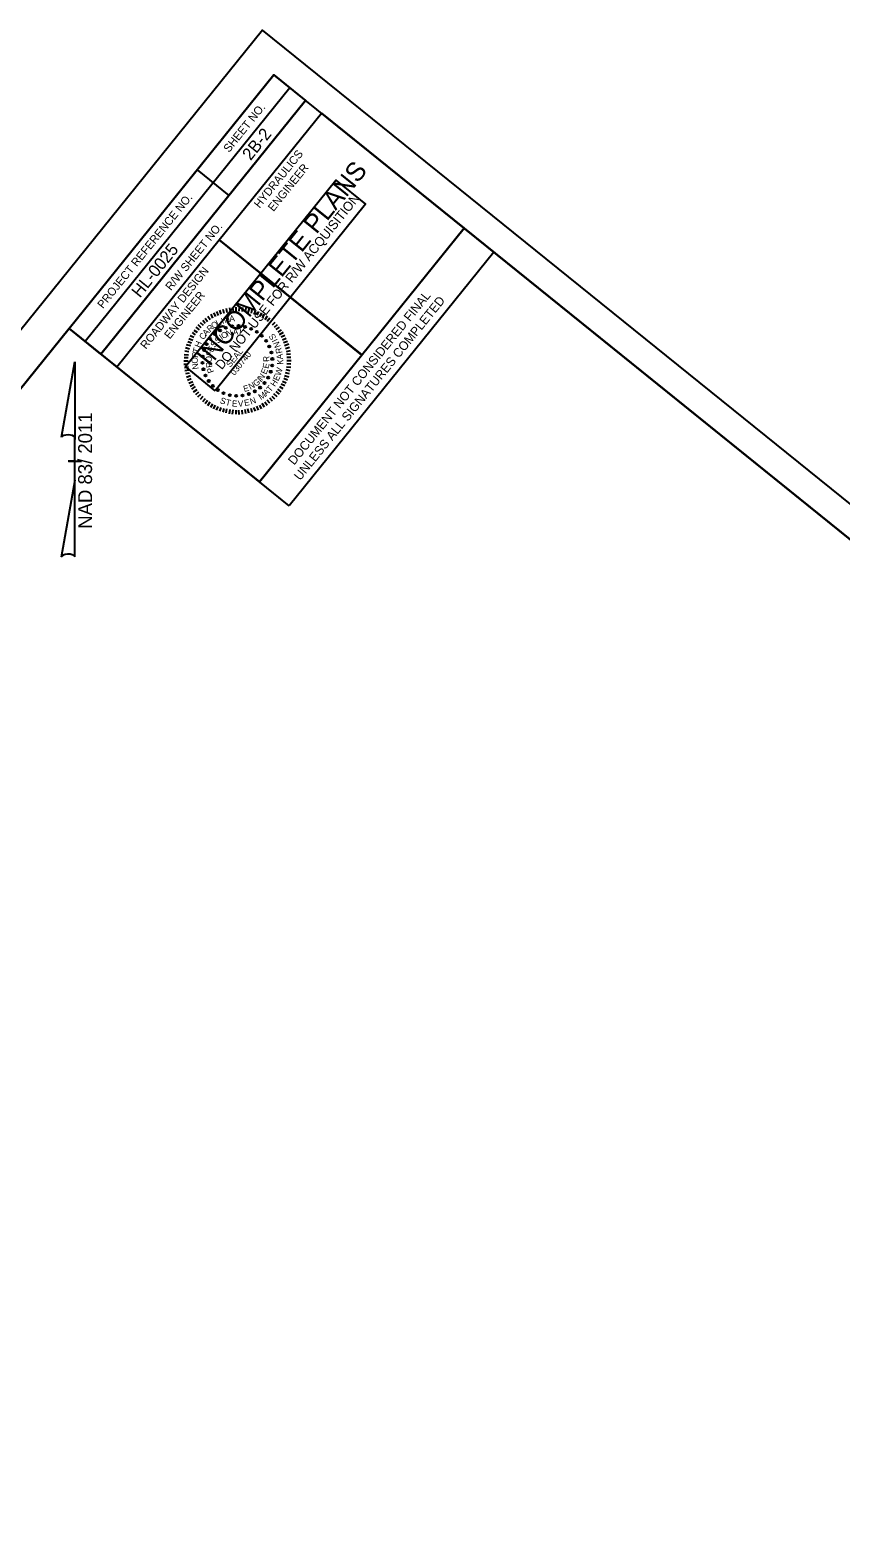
# Model space of a CAD drawing. Extents: x 1487845 to 1489754, y 498370 to 500368.
# Drawn here: x 1488759 to 1489256, y 499442 to 500368 of the extents above; entities that cross this region are included whole.
import ezdxf

# ---------------------------------------------------------------- set-up
doc = ezdxf.new("R2010")
doc.units = 0
for name, color, linetype in [('Old_Level_9', 7, 'Continuous'), ('Prop North Arrow NAD83 for Plan Sheets CELL', 7, 'Continuous'), ('Sheet Border Standard 30in CELL', 7, 'Continuous'), ('Sheet Clip Boundary CELL', 7, 'Continuous'), ('Sheet Data Field CELL', 7, 'Continuous'), ('Sheet Plan CELL', 7, 'Continuous'), ('Sheet Plot Border Outside CELL', 7, 'Continuous'), ('Sheet Sticker Exception Certification CELL', 7, 'Continuous'), ('Sheet Sticker Incomplete CELL', 7, 'Continuous')]:
    doc.layers.add(name, color=color, linetype=linetype)

msp = doc.modelspace()

# ---------------------------------------------------------------- linework, layer by layer
at = {"layer": 'Old_Level_9'}
for p, q in [((1488881.05, 500197.35), (1488881.45, 500194.97)), ((1488882.95, 500197.62), (1488883.29, 500195.03)), ((1488885.07, 500197.71), (1488885.12, 500195.23)), ((1488887.13, 500197.72), (1488886.9, 500195.2)), ((1488889.07, 500197.57), (1488888.84, 500195.06)), ((1488891.08, 500197.36), (1488890.71, 500194.83)), ((1488893.11, 500197.01), (1488892.46, 500194.45)), ((1488863.17, 500188.39), (1488864.91, 500186.73)), ((1488864.72, 500189.84), (1488866.28, 500187.94)), ((1488866.22, 500191.07), (1488867.65, 500189.02)), ((1488867.88, 500192.17), (1488869.31, 500190.12)), ((1488869.67, 500193.43), (1488870.78, 500190.99)), ((1488871.36, 500194.25), (1488872.59, 500192.1)), ((1488873.11, 500195.15), (1488874.23, 500192.71)), ((1488875.08, 500196), (1488875.85, 500193.45)), ((1488877.1, 500196.43), (1488877.72, 500194.01)), ((1488879.04, 500196.92), (1488879.59, 500194.42)), ((1488894.94, 500196.56), (1488894.49, 500194.1)), ((1488897.07, 500195.87), (1488896.06, 500193.34)), ((1488898.93, 500195.14), (1488897.9, 500192.76)), ((1488900.72, 500194.34), (1488899.54, 500192.08)), ((1488902.39, 500193.38), (1488901.27, 500191.2)), ((1488904.15, 500192.22), (1488902.75, 500190)), ((1488905.85, 500190.97), (1488904.28, 500189.03)), ((1488907.33, 500189.78), (1488905.76, 500187.84)), ((1488908.9, 500188.39), (1488907.23, 500186.64)), ((1488856.18, 500178.61), (1488858.57, 500177.59)), ((1488857.06, 500180.34), (1488859.24, 500179.23)), ((1488858.15, 500182.17), (1488860.14, 500180.82)), ((1488859.26, 500183.71), (1488861.32, 500182.43)), ((1488860.42, 500185.47), (1488862.45, 500183.84)), ((1488861.74, 500187.1), (1488863.58, 500185.24)), ((1488910.41, 500186.91), (1488908.51, 500185.36)), ((1488911.7, 500185.49), (1488909.58, 500183.98)), ((1488912.86, 500183.9), (1488910.75, 500182.4)), ((1488914.04, 500182.18), (1488911.71, 500180.72)), ((1488915.1, 500180.3), (1488912.78, 500179.34)), ((1488915.92, 500178.61), (1488913.68, 500177.59)), ((1488853.65, 500171.02), (1488856.27, 500170.44)), ((1488854.16, 500172.92), (1488856.51, 500172.18)), ((1488854.6, 500174.75), (1488857.23, 500174.17)), ((1488855.46, 500176.76), (1488857.76, 500175.8)), ((1488916.77, 500176.64), (1488914.3, 500175.81)), ((1488917.45, 500174.94), (1488914.92, 500174.03)), ((1488917.88, 500172.92), (1488915.47, 500172.16)), ((1488918.31, 500170.9), (1488915.87, 500170.43)), ((1488853.18, 500164.85), (1488855.81, 500164.78)), ((1488853.18, 500162.79), (1488855.67, 500162.84)), ((1488853.25, 500166.85), (1488855.74, 500166.76)), ((1488853.39, 500168.78), (1488856.05, 500168.57)), ((1488853.47, 500160.76), (1488855.92, 500161.09)), ((1488918.67, 500168.81), (1488916.07, 500168.6)), ((1488918.75, 500160.78), (1488916.1, 500161)), ((1488918.96, 500164.86), (1488916.25, 500164.85)), ((1488918.75, 500162.84), (1488916.25, 500162.93)), ((1488918.81, 500166.9), (1488916.4, 500166.79)), ((1488853.68, 500158.79), (1488856.2, 500159.2)), ((1488854.24, 500156.93), (1488856.68, 500157.4)), ((1488854.74, 500154.85), (1488857.14, 500155.75)), ((1488855.3, 500152.99), (1488857.69, 500153.88)), ((1488856.15, 500151.02), (1488858.59, 500152.13)), ((1488915.87, 500151.16), (1488913.63, 500152.2)), ((1488916.75, 500152.89), (1488914.51, 500153.93)), ((1488917.46, 500154.88), (1488914.89, 500155.68)), ((1488918.03, 500156.87), (1488915.48, 500157.52)), ((1488918.4, 500158.75), (1488915.92, 500159.34)), ((1488857.05, 500149.26), (1488859.33, 500150.5)), ((1488858.03, 500147.45), (1488860.28, 500148.97)), ((1488859.13, 500145.79), (1488861.24, 500147.3)), ((1488860.45, 500144.08), (1488862.41, 500145.71)), ((1488861.74, 500142.66), (1488863.54, 500144.41)), ((1488863.25, 500141.18), (1488864.96, 500143.14)), ((1488864.67, 500139.91), (1488866.39, 500141.73)), ((1488907.47, 500139.95), (1488905.84, 500141.9)), ((1488908.9, 500141.24), (1488907.22, 500142.98)), ((1488910.37, 500142.75), (1488908.41, 500144.46)), ((1488911.77, 500144.32), (1488909.82, 500145.89)), ((1488912.88, 500145.86), (1488910.74, 500147.34)), ((1488913.98, 500147.54), (1488911.93, 500148.81)), ((1488915.07, 500149.36), (1488912.81, 500150.55)), ((1488866.3, 500138.59), (1488867.71, 500140.66)), ((1488867.92, 500137.41), (1488869.32, 500139.63)), ((1488869.6, 500136.32), (1488870.86, 500138.51)), ((1488871.35, 500135.29), (1488872.45, 500137.62)), ((1488873.2, 500134.57), (1488874.24, 500136.81)), ((1488875.12, 500133.92), (1488876.08, 500136.23)), ((1488877.18, 500133.29), (1488877.78, 500135.63)), ((1488879.01, 500132.84), (1488879.53, 500135.25)), ((1488881.05, 500132.35), (1488881.56, 500134.89)), ((1488882.92, 500132.12), (1488883.29, 500134.65)), ((1488885.14, 500132.01), (1488885.15, 500134.57)), ((1488887.14, 500131.94), (1488886.93, 500134.54)), ((1488889.05, 500132.07), (1488888.91, 500134.62)), ((1488891.14, 500132.44), (1488890.66, 500134.87)), ((1488893.03, 500132.71), (1488892.4, 500135.27)), ((1488895.05, 500133.14), (1488894.35, 500135.62)), ((1488897.03, 500133.85), (1488896.14, 500136.24)), ((1488898.88, 500134.54), (1488897.84, 500136.92)), ((1488900.71, 500135.38), (1488899.69, 500137.62)), ((1488902.52, 500136.36), (1488901.28, 500138.64)), ((1488904.26, 500137.4), (1488902.9, 500139.53)), ((1488905.89, 500138.78), (1488904.34, 500140.68))]:
    msp.add_line(p, q, dxfattribs=at)
for centre in [(1488869.3, 500178.3), (1488872.08, 500181.14), (1488875.33, 500183.41), (1488878.94, 500185.05), (1488882.79, 500186), (1488886.75, 500186.22), (1488890.68, 500185.71), (1488894.45, 500184.49), (1488897.94, 500182.6), (1488901.02, 500180.1), (1488865.53, 500171.36), (1488867.1, 500175.01), (1488903.58, 500177.07), (1488905.55, 500173.63), (1488906.84, 500169.88), (1488864.53, 500163.53), (1488864.67, 500167.49), (1488865.11, 500159.61), (1488907.29, 500162), (1488907.43, 500165.96), (1488866.41, 500155.86), (1488868.38, 500152.42), (1488902.65, 500151.19), (1488904.86, 500154.49), (1488906.42, 500158.13), (1488870.94, 500149.39), (1488874.02, 500146.89), (1488877.51, 500145), (1488881.28, 500143.78), (1488885.21, 500143.27), (1488889.17, 500143.5), (1488893.02, 500144.44), (1488896.63, 500146.08), (1488899.88, 500148.36)]:
    msp.add_circle(centre, 0.63, dxfattribs=at)
at = {"layer": 'Prop North Arrow NAD83 for Plan Sheets CELL'}
for p, q in [((1488777.99, 500117.89), (1488786.19, 500164.24)), ((1488786.24, 500164.24), (1488786.19, 500164.24)), ((1488786.24, 500164.24), (1488786.19, 500164.24)), ((1488786.24, 500164.24), (1488786.24, 500116.44)), ((1488786.24, 500091.64), (1488786.24, 500117.84)), ((1488786.24, 500116.44), (1488786.24, 500117.79)), ((1488782.24, 500103.24), (1488782.19, 500103.24)), ((1488785.79, 500103.24), (1488782.24, 500103.24)), ((1488782.29, 500103.24), (1488790.29, 500103.24)), ((1488786.24, 500091.64), (1488777.89, 500044.39)), ((1488786.29, 500044.59), (1488786.24, 500091.64))]:
    msp.add_line(p, q, dxfattribs=at)
for centre, start_param, end_param in [((1488782.12, 500117.39), 0.216388, 2.908219), ((1488782.12, 500044.22), 0.201328, 3.141593)]:
    msp.add_ellipse(centre, major_axis=(4.23, -0.03), ratio=0.461098, start_param=start_param, end_param=end_param, dxfattribs=at)
at = {"layer": 'Sheet Border Standard 30in CELL'}
msp.add_line((1488802.23, 500168.98), (1488811.96, 500161.13), dxfattribs=at)
at = {"layer": 'Sheet Clip Boundary CELL'}
msp.add_lwpolyline([(1488917.84, 500075.78), (1488782.72, 500184.72), (1488048.03, 499273.68), (1488893.23, 498649.1), (1489725.65, 499681.3), (1489043.41, 500231.49)], close=True, dxfattribs=at)
at = {"layer": 'Sheet Plan CELL'}
for p, q in [((1488792.49, 500176.83), (1488918.08, 500332.55)), ((1488802.25, 500168.97), (1488927.81, 500324.7)), ((1488802.25, 500168.97), (1488927.81, 500324.7)), ((1488861.26, 500281.99), (1488880.75, 500266.33)), ((1488874.78, 500239.01), (1488962.33, 500168.43)), ((1488802.25, 500168.97), (1488811.97, 500161.13))]:
    msp.add_line(p, q, dxfattribs=at)
for points in [[(1488908.33, 500340.46), (1487966.68, 499172.8), (1488784.02, 498513.67), (1489725.65, 499681.3)], [(1488782.72, 500184.72), (1488908.33, 500340.46), (1488927.81, 500324.7), (1488802.25, 500168.97)], [(1488874.78, 500239.01), (1488937.54, 500316.85), (1489025.13, 500246.23), (1488962.36, 500168.38)], [(1488784.02, 498513.67), (1487966.69, 499172.77), (1488782.72, 500184.72), (1488899.54, 500090.53), (1489025.13, 500246.23), (1489725.65, 499681.3)], [(1488811.97, 500161.13), (1488874.78, 500239.01), (1488962.36, 500168.38), (1488899.54, 500090.53)]]:
    msp.add_lwpolyline(points, close=True, dxfattribs=at)
at = {"layer": 'Sheet Plot Border Outside CELL'}
msp.add_lwpolyline([(1488697.03, 498369.94), (1489753.85, 499680.4), (1488901.48, 500367.79), (1487844.66, 499057.32)], close=True, dxfattribs=at)
at = {"layer": 'Sheet Sticker Exception Certification CELL'}
for p, q in [((1488899.54, 500090.53), (1489025.12, 500246.24)), ((1488899.54, 500090.53), (1489025.12, 500246.24)), ((1489025.13, 500246.23), (1489043.42, 500231.48)), ((1489025.13, 500246.23), (1489043.42, 500231.48)), ((1489043.41, 500231.49), (1488917.84, 500075.78)), ((1489043.41, 500231.49), (1488917.84, 500075.78)), ((1488917.84, 500075.78), (1488899.54, 500090.53)), ((1488917.84, 500075.78), (1488899.54, 500090.53))]:
    msp.add_line(p, q, dxfattribs=at)
at = {"layer": 'Sheet Sticker Incomplete CELL'}
msp.add_lwpolyline([(1488872.43, 500146.49), (1488854.13, 500161.24), (1488946.41, 500275.67), (1488964.7, 500260.92)], close=True, dxfattribs=at)

# ---------------------------------------------------------------- texts
at = {"layer": 'Old_Level_9'}
for s, height, rotation, p in [('O', 3.78, 34.20245, (1488871.37, 500184.22)), ('L', 3.78, 26.86155, (1488873.95, 500185.99)), ('I', 3.78, 21.9216, (1488876.86, 500187.37)), ('N', 3.78, 16.01949, (1488878.22, 500187.94)), ('A', 3.78, 8.12072, (1488881.27, 500188.7)), ('C', 3.78, 56.05556, (1488865.27, 500177.45)), ('A', 3.78, 49.09051, (1488866.93, 500179.84)), ('R', 3.78, 41.1372, (1488869.16, 500182.28)), ('S', 3.76, 44.1571, (1488874.11, 500175.2)), ('I', 3.76, 36.59771, (1488876.43, 500177.44)), ('O', 3.76, 28.99053, (1488877.22, 500178.09)), ('N', 3.76, 18.50867, (1488879.77, 500179.5)), ('A', 3.76, 5.05942, (1488883.28, 500180.52)), ('L', 3.76, 352.64795, (1488886.89, 500180.69)), ('S', 3.78, 123.37353, (1488910.01, 500179.11)), ('R', 3.78, 83.2911, (1488861.74, 500166.55)), ('T', 3.78, 76.55143, (1488862.16, 500169.3)), ('H', 3.78, 68.859, (1488863.01, 500172.59)), ('F', 3.76, 77.5156, (1488870.4, 500167.41)), ('E', 3.76, 67.70458, (1488870.92, 500169.81)), ('S', 3.76, 55.58367, (1488872.18, 500172.65)), ('SEAL', 3.759, 51.11565, (1488881.61, 500160.5)), ('030740', 3.759, 51.11565, (1488884.24, 500155.54)), ('I', 3.78, 117.16204, (1488910.89, 500177.51)), ('N', 3.78, 110.48821, (1488912.63, 500173.62)), ('R', 3.78, 102.26596, (1488913.61, 500169.67)), ('A', 3.78, 94.63734, (1488913.96, 500165.84)), ('O', 3.78, 91.05986, (1488861.68, 500163.13)), ('N', 3.78, 99.1823, (1488862.25, 500159.85)), ('O', 3.76, 89.36746, (1488870.21, 500163.83)), ('R', 3.76, 100.86345, (1488870.73, 500160.97)), ('P', 3.76, 111.23929, (1488871.75, 500158.09)), ('E', 3.76, 66.92133, (1488903.6, 500156.17)), ('E', 3.76, 78.27246, (1488905.07, 500159.74)), ('R', 3.76, 91.46491, (1488905.59, 500164.21)), ('W', 3.78, 73.12141, (1488912.48, 500155.37)), ('K', 3.78, 87.25665, (1488914.07, 500162.37)), ('N', 3.76, 27.17401, (1488893.91, 500147.03)), ('G', 3.76, 38.59689, (1488897.36, 500148.75)), ('I', 3.76, 46.74023, (1488900.41, 500151.42)), ('N', 3.76, 54.24344, (1488901.17, 500152.36)), ('H', 3.78, 57.12686, (1488909.04, 500148.64)), ('E', 3.78, 65.2804, (1488911.06, 500152.07)), ('S', 3.78, 339.32765, (1488874.95, 500139)), ('E', 3.76, 15.98484, (1488890.22, 500145.64)), ('N', 3.78, 19.44464, (1488894.36, 500137.92)), ('M', 3.78, 33.45268, (1488900.4, 500140.64)), ('A', 3.78, 41.29781, (1488903.65, 500143.02)), ('T', 3.78, 48.50223, (1488906.22, 500145.32)), ('T', 3.78, 346.74003, (1488878.44, 500137.72)), ('E', 3.78, 354.93814, (1488882.48, 500136.86)), ('V', 3.78, 3.04544, (1488886.37, 500136.63)), ('E', 3.78, 11.34689, (1488890.5, 500137.01))]:
    msp.add_text(s, height=height, rotation=rotation, dxfattribs=at).set_placement(p)
at = {"layer": 'Prop North Arrow NAD83 for Plan Sheets CELL'}
msp.add_text('NAD 83/ 2011', height=8.5, rotation=90, dxfattribs=at).set_placement((1488796.76, 500061.72))
at = {"layer": 'Sheet Data Field CELL'}
for s, p in [('2B-2', (1488894.07, 500287.32)), ('HL-0025', (1488826.16, 500203.02))]:
    msp.add_text(s, height=7.5, rotation=51.11565, dxfattribs=at).set_placement(p)
at = {"layer": 'Sheet Plan CELL'}
for s, height, p in [('SHEET NO.', 5, (1488880.85, 500292.33)), ('HYDRAULICS', 5, (1488899.57, 500258.16)), ('ENGINEER', 5, (1488908.13, 500256.09)), ('PROJECT REFERENCE NO.', 5.0001, (1488803.45, 500196.53)), ('R/W SHEET NO.', 5.0001, (1488845.19, 500207.58)), ('ROADWAY DESIGN', 5.0001, (1488829.82, 500171.63)), ('ENGINEER', 5, (1488844.47, 500177.79))]:
    msp.add_text(s, height=height, rotation=51.11565, dxfattribs=at).set_placement(p)
at = {"layer": 'Sheet Sticker Exception Certification CELL'}
for s, p in [('DOCUMENT NOT CONSIDERED FINAL', (1488920.82, 500100.44)), ('DOCUMENT NOT CONSIDERED FINAL', (1488920.82, 500100.44)), ('UNLESS ALL SIGNATURES COMPLETED', (1488924.49, 500090.97)), ('UNLESS ALL SIGNATURES COMPLETED', (1488924.49, 500090.97))]:
    msp.add_text(s, height=5.5, rotation=51.11565, dxfattribs=at).set_placement(p)
at = {"layer": 'Sheet Sticker Incomplete CELL'}
for s, height, p in [('INCOMPLETE PLANS', 11.52, (1488868.94, 500160.8)), ('DO NOT USE FOR R/W ACQUISITION', 5.76, (1488876.39, 500158.97))]:
    msp.add_text(s, height=height, rotation=51.11565, dxfattribs=at).set_placement(p)

doc.saveas('drawing.dxf')
